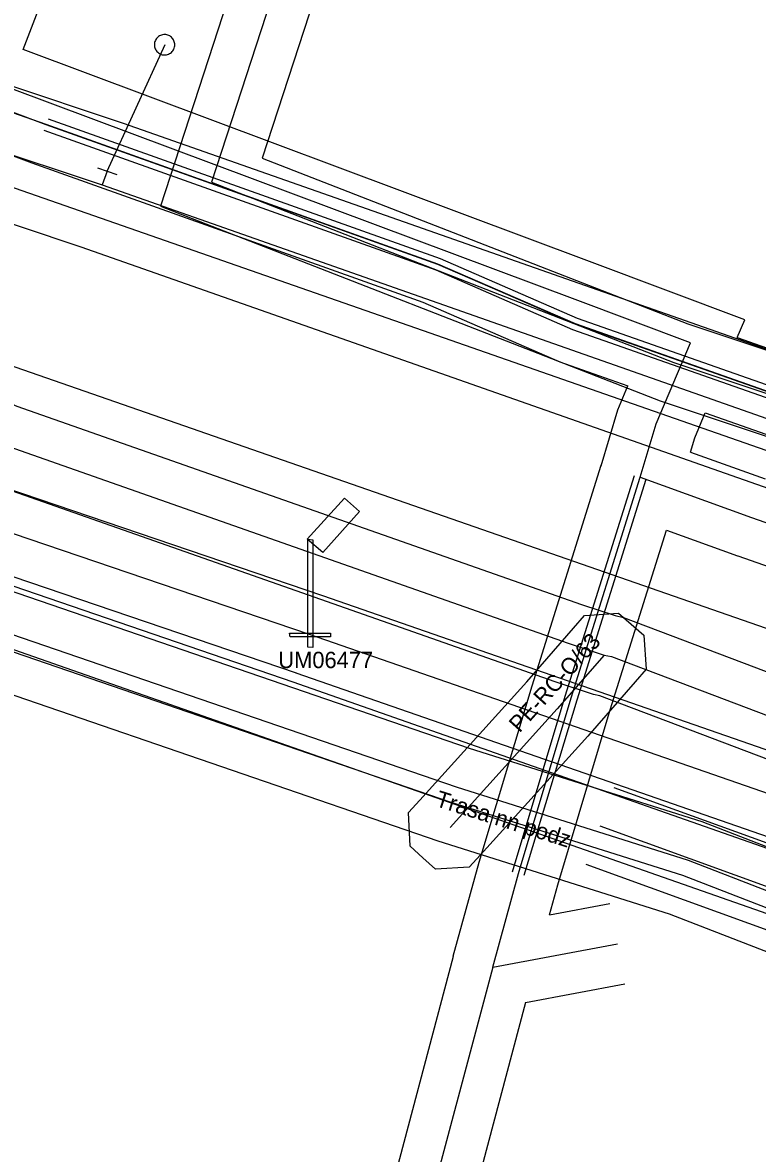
# Model space of a CAD drawing. Extents: x -762993 to -761845, y -975230 to -974501.
# Drawn here: x -762349.52 to -762331.54, y -974989.84 to -974962.16 of the extents above; entities that cross this region are included whole.
import ezdxf

# ---------------------------------------------------------------- set-up
doc = ezdxf.new("R2010")
doc.units = 0
for name, color, linetype in [('IS_CETIN_chranicka', 7, 'Continuous'), ('IS_CETIN_OP', 7, 'Continuous'), ('IS_CETIN_podzem metalika zam', 7, 'Continuous'), ('IS_CETIN_podzem NN', 7, 'Continuous'), ('IS_CETIN_podzem optika zam', 7, 'Continuous'), ('IS_CETIN_podzem out of order', 7, 'Continuous'), ('IS_CEZ-D_anotace', 7, 'Continuous'), ('IS_CEZ-D_el vedeni NN podzem', 7, 'Continuous'), ('IS_CEZ-D_el vedeni VN podzem', 7, 'Continuous'), ('IS_CEZ-D_OP', 7, 'Continuous'), ('IS_CRA_podzem telekomunikace', 7, 'Continuous'), ('IS_DPmUL_OP', 7, 'Continuous'), ('IS_DPmUL_VO lampy', 7, 'Continuous'), ('IS_DPmUL_VO lampy anotace', 7, 'Continuous'), ('IS_DPmUL_VO vedeni podzem', 7, 'Continuous'), ('IS_GASNET_plyn NTL anotace', 7, 'Continuous'), ('IS_GASNET_plyn NTL pripojky', 7, 'Continuous'), ('IS_GASNET_plyn NTL rad', 7, 'Continuous'), ('IS_GASNET_plyn OP', 7, 'Continuous'), ('IS_SCVK_kanalizace jednotna', 7, 'Continuous'), ('IS_SCVK_vodovod OP', 7, 'Continuous'), ('IS_SCVK_vodovod pripojky', 7, 'Continuous'), ('IS_SCVK_vodovod privadec', 7, 'Continuous'), ('IS_SCVK_vodovod znaky', 7, 'Continuous'), ('IS_T-Mobile_OP', 7, 'Continuous'), ('IS_T-Mobile_podzem optika', 7, 'Continuous'), ('IS_vodafone_podzem metalika', 7, 'Continuous')]:
    doc.layers.add(name, color=color, linetype=linetype)

msp = doc.modelspace()

# ---------------------------------------------------------------- linework, layer by layer
at = {"layer": 'IS_CETIN_chranicka'}
for points in [[(-762348.9, -974964.509), (-762339.305, -974967.93), (-762335.955, -974969.39), (-762326.242, -974972.808), (-762323.694, -974973.617), (-762321.565, -974974.32), (-762319.618, -974975.203)], [(-762349, -974964.791), (-762339.415, -974968.21), (-762336.065, -974969.67), (-762326.338, -974973.092), (-762323.786, -974973.903), (-762321.675, -974974.6), (-762319.742, -974975.477)], [(-762337.534, -974982.947), (-762336.243, -974978.646), (-762334.553, -974973.245)], [(-762337.246, -974983.033), (-762335.957, -974978.734), (-762334.267, -974973.335)]]:
    msp.add_lwpolyline(points, dxfattribs=at)
at = {"layer": 'IS_CETIN_OP'}
for p, q in [((-762349.508, -974962.816), (-762347.165, -974956.655)), ((-762335.649, -974968.003), (-762349.508, -974962.816)), ((-762333.182, -974972.67), (-762331.351, -974973.329)), ((-762333.767, -974974.584), (-762332.029, -974975.211)), ((-762336.632, -974984.003), (-762335.154, -974983.727)), ((-762337.216, -974986.147), (-762334.786, -974985.693))]:
    msp.add_line(p, q, dxfattribs=at)
for points in [[(-762419.297, -974940.826), (-762417.443, -974941.715), (-762392.53, -974950.444), (-762377.95, -974955.514), (-762367.103, -974959.323), (-762363.702, -974960.533), (-762351.079, -974964.921), (-762349.293, -974965.589), (-762339.728, -974969), (-762336.376, -974970.461), (-762334.711, -974971.047)], [(-762332.038, -974969.868), (-762331.852, -974969.431), (-762335.648, -974968.004)], [(-762332.038, -974969.868), (-762325.973, -974972.002), (-762323.432, -974972.809), (-762321.256, -974973.527), (-762318.954, -974974.571), (-762318.136, -974976.13), (-762306.451, -974980.321), (-762300.467, -974981.8), (-762292.097, -974984.68), (-762290.767, -974985.008), (-762288.807, -974984.163), (-762287.974, -974982.862), (-762287.982, -974982.827), (-762289.282, -974980.773), (-762286.601, -974981.001), (-762284.415, -974982.166)], [(-762335.368, -974973.005), (-762334.962, -974971.641), (-762334.711, -974971.047)], [(-762333.182, -974972.67), (-762333.078, -974972.319), (-762332.82, -974971.712)], [(-762332.82, -974971.712), (-762326.607, -974973.898), (-762325.23, -974974.336)], [(-762338.984, -974985.015), (-762338.351, -974982.714), (-762337.056, -974978.397), (-762335.364, -974972.991)], [(-762336.632, -974984.003), (-762336.429, -974983.266), (-762335.144, -974978.983), (-762333.767, -974974.584)], [(-762332.021, -974975.214), (-762325.111, -974977.634)], [(-762338.986, -974985.023), (-762340.695, -974991.456), (-762341.567, -974992.303)], [(-762337.216, -974986.147), (-762338.905, -974992.504), (-762339.836, -974993.409)]]:
    msp.add_lwpolyline(points, dxfattribs=at)
at = {"layer": 'IS_CETIN_podzem metalika zam'}
msp.add_lwpolyline([(-762338.02, -974985.28), (-762334.97, -974984.71)], dxfattribs=at)
at = {"layer": 'IS_CETIN_podzem NN'}
for points in [[(-762336, -974968.94), (-762350.8, -974963.4)], [(-762334.41, -974973.29), (-762334.02, -974971.98), (-762333.18, -974970), (-762336, -974968.94)], [(-762338.02, -974985.28), (-762337.39, -974982.99), (-762336.1, -974978.69), (-762334.41, -974973.29)], [(-762338.02, -974985.28), (-762339.8, -974991.98), (-762340.87, -974993.02)]]:
    msp.add_lwpolyline(points, dxfattribs=at)
at = {"layer": 'IS_CETIN_podzem optika zam'}
for points in [[(-762377.62, -974954.57), (-762366.77, -974958.38), (-762363.37, -974959.59), (-762350.74, -974963.98), (-762348.95, -974964.65), (-762339.36, -974968.07), (-762336.01, -974969.53), (-762326.29, -974972.95), (-762323.74, -974973.76), (-762321.62, -974974.46), (-762319.68, -974975.34), (-762318.84, -974976.94), (-762306.74, -974981.28), (-762300.75, -974982.76), (-762292.38, -974985.64), (-762290.68, -974986.06), (-762288.13, -974984.96), (-762286.9, -974983.04), (-762287.05, -974982.43), (-762287.36, -974981.94), (-762286.89, -974981.98), (-762283.27, -974983.91), (-762274.13, -974988.8), (-762260.53, -974993.46)], [(-762336, -974968.94), (-762350.8, -974963.4)], [(-762334.41, -974973.29), (-762334.02, -974971.98), (-762333.18, -974970), (-762336, -974968.94)], [(-762338.02, -974985.28), (-762337.39, -974982.99), (-762336.1, -974978.69), (-762334.41, -974973.29)], [(-762334.41, -974973.29), (-762331.69, -974974.27)], [(-762331.69, -974974.27), (-762324.78, -974976.69)], [(-762338.02, -974985.28), (-762339.8, -974991.98), (-762340.87, -974993.02)]]:
    msp.add_lwpolyline(points, dxfattribs=at)
at = {"layer": 'IS_CETIN_podzem out of order'}
for points in [[(-762377.04, -974956.66), (-762339.91, -974969.63), (-762327.23, -974974.06)], [(-762393.36, -974970.49), (-762394.76, -974970.05), (-762391.76, -974961.27), (-762386.9, -974962.9), (-762371.15, -974968.61), (-762342.91, -974978.3), (-762324.01, -974984.93), (-762322.43, -974985.48)]]:
    msp.add_lwpolyline(points, dxfattribs=at)
at = {"layer": 'IS_CEZ-D_el vedeni NN podzem'}
for points in [[(-762394.922, -974961.348), (-762366.691, -974971.325), (-762338.912, -974980.87), (-762333.235, -974982.66), (-762317.369, -974988.815), (-762313.901, -974990.502), (-762312.492, -974990.931), (-762308.55, -974979.749), (-762308.284, -974978.995), (-762308.259, -974979.004), (-762304.782, -974980.906), (-762293.136, -974984.559), (-762291.208, -974984.727), (-762288.899, -974984.279), (-762285.346, -974981.506), (-762284.881, -974980.325), (-762284.547, -974977.953), (-762290.432, -974954.683), (-762291.314, -974953.684), (-762291.816, -974954.174), (-762292.054, -974954.011)], [(-762342.967, -974959.546), (-762342.778, -974959.612), (-762343.206, -974960.852), (-762344.903, -974966.065), (-762333.585, -974970.475), (-762322.985, -974974.011), (-762312.522, -974977.213), (-762309.333, -974978.189), (-762308.125, -974978.628), (-762304.826, -974980.473), (-762293.058, -974984.165), (-762291.229, -974984.323), (-762289.07, -974983.904), (-762285.678, -974981.258), (-762285.27, -974980.222), (-762284.953, -974977.971), (-762290.8, -974954.871), (-762291.335, -974954.264), (-762291.585, -974954.509), (-762292.054, -974954.011)], [(-762312.434, -975011.429), (-762311.562, -975011.492), (-762311.55, -975011.669), (-762308.991, -975012.245), (-762308.787, -975011.452), (-762307.552, -975006.66), (-762307.854, -974999.844), (-762312.234, -974993.249), (-762317.513, -974989.187), (-762333.367, -974983.038), (-762339.038, -974981.25), (-762354.832, -974975.823), (-762355.035, -974975.753), (-762355.226, -974976.23), (-762356.629, -974979.736), (-762357.615, -974982.215), (-762357.804, -974982.149)]]:
    msp.add_lwpolyline(points, dxfattribs=at)
at = {"layer": 'IS_CEZ-D_el vedeni VN podzem'}
msp.add_lwpolyline([(-762322.36, -974987.09), (-762324.59, -974986.24), (-762328.28, -974985.04), (-762360.05, -974973.9), (-762363.79, -974972.56), (-762395.59, -974961.56), (-762398.7, -974960.48), (-762421.28, -974952.57), (-762425.16, -974951.24), (-762434.97, -974947.57)], dxfattribs=at)
at = {"layer": 'IS_CEZ-D_OP'}
for points in [[(-762425.326, -974953.474), (-762425.823, -974952.392), (-762424.284, -974951.508), (-762423.951, -974951.317), (-762421.468, -974950.868), (-762394.588, -974960.405), (-762366.362, -974970.381), (-762338.599, -974979.92), (-762332.903, -974981.716), (-762317.463, -974987.706)], [(-762343.396, -974958.337), (-762344.154, -974960.534), (-762346.146, -974966.654), (-762333.925, -974971.416), (-762323.29, -974974.964), (-762312.815, -974978.169), (-762309.65, -974979.138), (-762309.424, -974979.22)], [(-762343.396, -974958.337), (-762341.508, -974958.996), (-762342.258, -974961.17), (-762343.66, -974965.476), (-762333.245, -974969.534), (-762322.68, -974973.058), (-762312.229, -974976.257), (-762309.016, -974977.24), (-762307.707, -974977.716), (-762305.235, -974979.099)], [(-762312.622, -975010.413), (-762310.623, -975010.557), (-762310.603, -975010.857), (-762309.718, -975011.056), (-762308.558, -975006.555), (-762308.841, -975000.166), (-762312.975, -974993.94), (-762318.009, -974990.067), (-762333.698, -974983.982), (-762339.351, -974982.2), (-762354.46, -974977.008), (-762355.7, -974980.107), (-762357.04, -974983.475), (-762358.93, -974982.815)]]:
    msp.add_lwpolyline(points, dxfattribs=at)
at = {"layer": 'IS_CRA_podzem telekomunikace'}
msp.add_lwpolyline([(-762286.963, -974982.858), (-762286.915, -974983.05), (-762288.133, -974984.967), (-762290.685, -974986.061), (-762292.389, -974985.635), (-762300.689, -974982.775), (-762306.75, -974981.275), (-762318.851, -974976.949), (-762319.685, -974975.352), (-762321.623, -974974.461), (-762323.743, -974973.764), (-762326.285, -974972.953), (-762335.993, -974969.53), (-762339.363, -974968.07), (-762348.947, -974964.652), (-762363.377, -974959.593), (-762377.637, -974954.573), (-762392.217, -974949.493), (-762417.036, -974940.799), (-762419.044, -974939.84), (-762421.242, -974939.701), (-762425.393, -974938.364)], dxfattribs=at)
at = {"layer": 'IS_DPmUL_OP'}
for points in [[(-762371.192, -974966.319), (-762342.187, -974976.181)], [(-762371.836, -974968.213), (-762342.831, -974978.075)], [(-762342.181, -974976.183), (-762314.929, -974985.655)], [(-762342.837, -974978.073), (-762315.585, -974987.545)]]:
    msp.add_lwpolyline(points, dxfattribs=at)
at = {"layer": 'IS_DPmUL_VO lampy'}
for points in [[(-762341.649, -974973.798), (-762341.279, -974974.128), (-762342.179, -974975.128), (-762342.559, -974974.808)], [(-762342.539, -974974.808), (-762342.419, -974974.818), (-762342.419, -974977.458), (-762342.539, -974977.448)], [(-762342.989, -974977.108), (-762341.989, -974977.108), (-762341.989, -974977.198), (-762342.979, -974977.198)]]:
    msp.add_lwpolyline(points, close=True, dxfattribs=at)
at = {"layer": 'IS_DPmUL_VO vedeni podzem'}
for points in [[(-762371.514, -974967.266), (-762342.509, -974977.128)], [(-762342.509, -974977.128), (-762315.257, -974986.6)]]:
    msp.add_lwpolyline(points, dxfattribs=at)
at = {"layer": 'IS_GASNET_plyn NTL pripojky'}
msp.add_lwpolyline([(-762335.29, -974977.64), (-762336.44, -974978.96), (-762339.06, -974981.86)], dxfattribs=at)
at = {"layer": 'IS_GASNET_plyn NTL rad'}
msp.add_lwpolyline([(-762416.145, -974949.855), (-762381.041, -974961.735), (-762378.19, -974962.7), (-762377.47, -974962.93), (-762377.29, -974962.99), (-762377.092, -974963.051), (-762377.03, -974963.07), (-762356.37, -974970.3), (-762354.158, -974971.062), (-762353.96, -974971.13), (-762350.61, -974972.23), (-762350.171, -974972.416), (-762350.02, -974972.48), (-762336.17, -974977.35), (-762335.29, -974977.64), (-762335.11, -974977.68), (-762305.627, -974988.849), (-762305.14, -974989.03), (-762304.73, -974989.2), (-762303.75, -974989.6), (-762303.207, -974990.005), (-762302.681, -974990.396), (-762302.34, -974990.65)], dxfattribs=at)
at = {"layer": 'IS_GASNET_plyn OP'}
for points in [[(-762376.718, -974962.12), (-762356.042, -974969.355), (-762353.833, -974970.116), (-762353.642, -974970.182), (-762350.258, -974971.293), (-762349.781, -974971.495), (-762349.659, -974971.547), (-762335.848, -974976.403), (-762335.024, -974976.675), (-762334.823, -974976.719), (-762305.276, -974987.913)], [(-762305.978, -974989.785), (-762335.397, -974978.641), (-762335.556, -974978.605), (-762336.492, -974978.297), (-762350.381, -974973.413), (-762350.561, -974973.337), (-762350.962, -974973.167), (-762354.278, -974972.078), (-762354.483, -974972.008), (-762356.698, -974971.245), (-762377.342, -974964.02)]]:
    msp.add_lwpolyline(points, dxfattribs=at)
msp.add_lwpolyline([(-762334.264, -974977.985), (-762334.536, -974978.297), (-762335.692, -974979.624), (-762338.318, -974982.53), (-762338.596, -974982.837), (-762339.423, -974982.88), (-762339.73, -974982.602), (-762340.037, -974982.324), (-762340.08, -974981.497), (-762339.802, -974981.19), (-762337.188, -974978.296), (-762336.044, -974976.983), (-762335.772, -974976.671), (-762334.945, -974976.614), (-762334.633, -974976.886), (-762334.321, -974977.158)], close=True, dxfattribs=at)
at = {"layer": 'IS_SCVK_kanalizace jednotna'}
msp.add_lwpolyline([(-762373.865, -974962.18), (-762330.791, -974977.171)], dxfattribs=at)
at = {"layer": 'IS_SCVK_vodovod OP'}
for points in [[(-762370.788, -974956.301), (-762365.679, -974958.103), (-762364.905, -974958.37), (-762350.036, -974963.625), (-762347.061, -974964.615), (-762327.066, -974971.647), (-762323.688, -974972.721), (-762321.219, -974973.584), (-762302.563, -974980.135), (-762292.067, -974983.465), (-762286.179, -974984.538), (-762284.497, -974984.727), (-762283.191, -974984.34)], [(-762371.852, -974959.319), (-762366.733, -974961.125), (-762365.959, -974961.392), (-762351.074, -974966.651), (-762348.097, -974967.643), (-762328.082, -974974.681), (-762324.702, -974975.757), (-762322.277, -974976.604), (-762303.577, -974983.171), (-762292.841, -974986.577), (-762286.645, -974987.706), (-762284.209, -974987.979), (-762282.49, -974987.47)]]:
    msp.add_lwpolyline(points, dxfattribs=at)
at = {"layer": 'IS_SCVK_vodovod pripojky'}
msp.add_lwpolyline([(-762347.456, -974965.793), (-762346.033, -974962.692)], dxfattribs=at)
at = {"layer": 'IS_SCVK_vodovod privadec'}
msp.add_lwpolyline([(-762371.32, -974957.81), (-762366.206, -974959.614), (-762365.432, -974959.881), (-762350.555, -974965.138), (-762347.579, -974966.129), (-762327.574, -974973.164), (-762324.195, -974974.239), (-762321.748, -974975.094), (-762303.07, -974981.653), (-762292.454, -974985.021), (-762286.412, -974986.122), (-762284.353, -974986.353), (-762281.669, -974985.558)], dxfattribs=at)
at = {"layer": 'IS_SCVK_vodovod znaky'}
for points in [[(-762346.296, -974962.67), (-762346.297, -974962.696)], [(-762346.296, -974962.67), (-762346.297, -974962.696)], [(-762346.292, -974962.644), (-762346.296, -974962.67)], [(-762346.292, -974962.644), (-762346.296, -974962.67)], [(-762346.284, -974962.619), (-762346.292, -974962.644)], [(-762346.284, -974962.619), (-762346.292, -974962.644)], [(-762346.274, -974962.595), (-762346.284, -974962.619)], [(-762346.274, -974962.595), (-762346.284, -974962.619)], [(-762346.263, -974962.571), (-762346.274, -974962.595)], [(-762346.263, -974962.571), (-762346.274, -974962.595)], [(-762346.248, -974962.55), (-762346.263, -974962.571)], [(-762346.248, -974962.55), (-762346.263, -974962.571)], [(-762346.231, -974962.53), (-762346.248, -974962.55)], [(-762346.231, -974962.53), (-762346.248, -974962.55)], [(-762346.213, -974962.511), (-762346.231, -974962.53)], [(-762346.213, -974962.511), (-762346.231, -974962.53)], [(-762346.193, -974962.495), (-762346.213, -974962.511)], [(-762346.193, -974962.495), (-762346.213, -974962.511)], [(-762346.17, -974962.481), (-762346.193, -974962.495)], [(-762346.17, -974962.481), (-762346.193, -974962.495)], [(-762346.147, -974962.47), (-762346.17, -974962.481)], [(-762346.147, -974962.47), (-762346.17, -974962.481)], [(-762346.122, -974962.461), (-762346.147, -974962.47)], [(-762346.122, -974962.461), (-762346.147, -974962.47)], [(-762346.096, -974962.453), (-762346.122, -974962.461)], [(-762346.096, -974962.453), (-762346.122, -974962.461)], [(-762346.07, -974962.45), (-762346.096, -974962.453)], [(-762346.07, -974962.45), (-762346.096, -974962.453)], [(-762346.045, -974962.449), (-762346.07, -974962.45)], [(-762346.045, -974962.449), (-762346.07, -974962.45)], [(-762346.018, -974962.451), (-762346.045, -974962.449)], [(-762346.018, -974962.451), (-762346.045, -974962.449)], [(-762345.993, -974962.455), (-762346.018, -974962.451)], [(-762345.993, -974962.455), (-762346.018, -974962.451)], [(-762345.967, -974962.462), (-762345.993, -974962.455)], [(-762345.967, -974962.462), (-762345.993, -974962.455)], [(-762345.943, -974962.472), (-762345.967, -974962.462)], [(-762345.943, -974962.472), (-762345.967, -974962.462)], [(-762345.92, -974962.484), (-762345.943, -974962.472)], [(-762345.92, -974962.484), (-762345.943, -974962.472)], [(-762345.899, -974962.498), (-762345.92, -974962.484)], [(-762345.899, -974962.498), (-762345.92, -974962.484)], [(-762345.878, -974962.515), (-762345.899, -974962.498)], [(-762345.878, -974962.515), (-762345.899, -974962.498)], [(-762345.86, -974962.534), (-762345.878, -974962.515)], [(-762345.86, -974962.534), (-762345.878, -974962.515)], [(-762345.844, -974962.555), (-762345.86, -974962.534)], [(-762345.844, -974962.555), (-762345.86, -974962.534)], [(-762345.829, -974962.577), (-762345.844, -974962.555)], [(-762345.829, -974962.577), (-762345.844, -974962.555)], [(-762345.818, -974962.6), (-762345.829, -974962.577)], [(-762345.818, -974962.6), (-762345.829, -974962.577)], [(-762345.81, -974962.624), (-762345.818, -974962.6)], [(-762345.81, -974962.624), (-762345.818, -974962.6)], [(-762345.802, -974962.65), (-762345.81, -974962.624)], [(-762345.802, -974962.65), (-762345.81, -974962.624)], [(-762345.799, -974962.676), (-762345.802, -974962.65)], [(-762345.799, -974962.676), (-762345.802, -974962.65)], [(-762346.297, -974962.696), (-762346.297, -974962.722)], [(-762346.297, -974962.696), (-762346.297, -974962.722)], [(-762346.297, -974962.722), (-762346.292, -974962.747)], [(-762346.297, -974962.722), (-762346.292, -974962.747)], [(-762346.292, -974962.747), (-762346.286, -974962.773)], [(-762346.292, -974962.747), (-762346.286, -974962.773)], [(-762346.286, -974962.773), (-762346.277, -974962.798)], [(-762346.286, -974962.773), (-762346.277, -974962.798)], [(-762346.277, -974962.798), (-762346.265, -974962.822)], [(-762346.277, -974962.798), (-762346.265, -974962.822)], [(-762346.265, -974962.822), (-762346.251, -974962.843)], [(-762346.265, -974962.822), (-762346.251, -974962.843)], [(-762346.251, -974962.843), (-762346.236, -974962.864)], [(-762346.251, -974962.843), (-762346.236, -974962.864)], [(-762346.236, -974962.864), (-762346.217, -974962.883)], [(-762346.236, -974962.864), (-762346.217, -974962.883)], [(-762346.217, -974962.883), (-762346.198, -974962.899)], [(-762346.217, -974962.883), (-762346.198, -974962.899)], [(-762346.198, -974962.899), (-762346.175, -974962.914)], [(-762346.198, -974962.899), (-762346.175, -974962.914)], [(-762346.175, -974962.914), (-762346.152, -974962.925)], [(-762346.175, -974962.914), (-762346.152, -974962.925)], [(-762346.152, -974962.925), (-762346.128, -974962.936)], [(-762346.152, -974962.925), (-762346.128, -974962.936)], [(-762346.128, -974962.936), (-762346.103, -974962.942)], [(-762346.128, -974962.936), (-762346.103, -974962.942)], [(-762346.103, -974962.942), (-762346.077, -974962.947)], [(-762346.103, -974962.942), (-762346.077, -974962.947)], [(-762346.025, -974962.947), (-762345.998, -974962.944)], [(-762346.025, -974962.947), (-762345.998, -974962.944)], [(-762345.998, -974962.944), (-762345.974, -974962.938)], [(-762345.998, -974962.944), (-762345.974, -974962.938)], [(-762345.974, -974962.938), (-762345.949, -974962.927)], [(-762345.974, -974962.938), (-762345.949, -974962.927)], [(-762345.949, -974962.927), (-762345.925, -974962.917)], [(-762345.949, -974962.927), (-762345.925, -974962.917)], [(-762345.925, -974962.917), (-762345.904, -974962.903)], [(-762345.925, -974962.917), (-762345.904, -974962.903)], [(-762345.904, -974962.903), (-762345.882, -974962.887)], [(-762345.904, -974962.903), (-762345.882, -974962.887)], [(-762345.882, -974962.887), (-762345.864, -974962.868)], [(-762345.882, -974962.887), (-762345.864, -974962.868)], [(-762345.864, -974962.868), (-762345.847, -974962.848)], [(-762345.864, -974962.868), (-762345.847, -974962.848)], [(-762345.847, -974962.848), (-762345.833, -974962.826)], [(-762345.847, -974962.848), (-762345.833, -974962.826)], [(-762345.833, -974962.826), (-762345.821, -974962.803)], [(-762345.833, -974962.826), (-762345.821, -974962.803)], [(-762345.821, -974962.803), (-762345.811, -974962.779)], [(-762345.821, -974962.803), (-762345.811, -974962.779)], [(-762345.811, -974962.779), (-762345.803, -974962.753)], [(-762345.811, -974962.779), (-762345.803, -974962.753)], [(-762345.803, -974962.753), (-762345.799, -974962.728)], [(-762345.803, -974962.753), (-762345.799, -974962.728)], [(-762345.799, -974962.728), (-762345.798, -974962.702)], [(-762345.799, -974962.728), (-762345.798, -974962.702)], [(-762345.798, -974962.702), (-762345.799, -974962.676)], [(-762345.798, -974962.702), (-762345.799, -974962.676)], [(-762346.077, -974962.947), (-762346.051, -974962.949)], [(-762346.077, -974962.947), (-762346.051, -974962.949)], [(-762346.051, -974962.949), (-762346.025, -974962.947)], [(-762346.051, -974962.949), (-762346.025, -974962.947)], [(-762347.692, -974965.71), (-762347.22, -974965.876)], [(-762347.456, -974965.793), (-762347.579, -974966.129)]]:
    msp.add_lwpolyline(points, dxfattribs=at)
at = {"layer": 'IS_T-Mobile_OP'}
for p, q in [((-762325.067, -974984.513), (-762335.047, -974980.89)), ((-762325.713, -974986.407), (-762335.729, -974982.77))]:
    msp.add_line(p, q, dxfattribs=at)
at = {"layer": 'IS_T-Mobile_podzem optika'}
msp.add_lwpolyline([(-762325.39, -974985.46), (-762335.388, -974981.83)], dxfattribs=at)
msp.add_lwpolyline([(-762325.39, -974985.46), (-762335.388, -974981.83)], dxfattribs=at)
at = {"layer": 'IS_vodafone_podzem metalika'}
for p, q in [((-762339.36, -974968.08), (-762348.95, -974964.65)), ((-762336.01, -974969.53), (-762339.36, -974968.08)), ((-762326.3, -974972.96), (-762336.01, -974969.53))]:
    msp.add_line(p, q, dxfattribs=at)

# ---------------------------------------------------------------- texts
at = {"layer": 'IS_CEZ-D_anotace'}
msp.add_text('Trasa nn podz', height=0.4, rotation=342.4996, dxfattribs=at).set_placement((-762339.443, -974981.332))
at = {"layer": 'IS_DPmUL_VO lampy anotace'}
msp.add_text('UM06477', height=0.4, dxfattribs=at).set_placement((-762343.265, -974977.961))
at = {"layer": 'IS_GASNET_plyn NTL anotace'}
msp.add_text('PE-RC-O/63', height=0.4, rotation=47.9038, dxfattribs=at).set_placement((-762337.363, -974979.56))

doc.saveas('drawing.dxf')
